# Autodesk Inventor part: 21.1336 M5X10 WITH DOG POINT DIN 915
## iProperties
IsCustomPart: 1
Created: 2006-02
Part Number: 21.1336 M5X10 WITH DOG POINT DIN 915
Material: Steel, Mild
Description: M5X10 SET SCREW WITH DOG POINT DIN 915
Document SubType Name: Modeling
Standard: DIN 915
Designer: Andy Moles
Standards Organization: DIN
Language: en-US
Size Designation: M5 x 10
Categories: <MemberInstance><Categories><Category DisplayName="Fasteners" InternalName="e4da775c-781d-43d5-af7c-5136215cf5a6" Mnemonic="FSTN"><Category DisplayName="Bolts"
Density: 7.86 g/cm^3
Mass: 1.15986 g
Surface Area: 1.9956 cm^2
Volume: 0.147565 cm^3
Author: Andy Moles
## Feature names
1. Body [Revolution]
2. Chamfer1
3. Slot [Extrusion]
4. Chamfer2
